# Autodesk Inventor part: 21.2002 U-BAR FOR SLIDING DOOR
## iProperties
Created: 2007-05
Part Number: 21.2002 U-BAR FOR SLIDING DOOR
Material: Steel
Document SubType Name: Modeling
Designer: Andy Moles
Density: 7.85 g/cm^3
Mass: 127.594 g
Surface Area: 70.7629 cm^2
Volume: 16.2541 cm^3
Author: Andy Moles
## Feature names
1. Base1
